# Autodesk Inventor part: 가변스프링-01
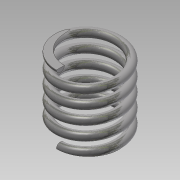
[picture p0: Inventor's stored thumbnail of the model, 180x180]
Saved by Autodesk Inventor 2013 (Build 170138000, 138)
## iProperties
Created: 2014-12
Part Number: 가변스프링-01
Material: 강철, 탄소
Document SubType Name: Modeling
Designer: hanacad19
Density: 7.87 g/cm^3
Mass: 18.7418 g
Surface Area: 32.4001 cm^2
Volume: 2.38143 cm^3
Author: hanacad19
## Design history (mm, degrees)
sketch "스케치1"
  geometry: L1 (0, 0)-(-11, 0); L2 (-11, 0)-(-11, 25.358); L3 (-11, 25.358)-(0, 25.358); L4 (0, 25.358)-(0, 0); C1 r 1.5 at (-11, 0)
  constraints: 8 end point, 2 parallel, 1 centre point, 1 horizontal, 1 perpendicular
  dimensions: "d0" = 3 diameter of C1; "d2" = 22 diameter of L2 L4; "d3" = 25.35829 distance between parallel lines of L1 L3 (derived)
feature "코일1" sketch "스케치1" pitch "d4" = 10; turns "d6" = 5; dims "d5" = 25.35829 (= d3), "d7" = 0, angle "d8" = 90 deg, angle "d9" = 90 deg, "d10" = 0, "d11" = 0
sketch "스케치2"
  geometry: L1 (0, -12.5)-(0, -9.5) reference; 1 further point
  constraints: 1 vertical alignment
extrude "돌출1" cut sketch "스케치2" distance "d12" = 10; taper "d13" = 0 deg
node "작업 평면1"
sketch "스케치3"
  geometry: L1 (0, -9.5)-(0, -12.5) reference; 1 further point
  constraints: 1 vertical alignment
extrude "돌출2" cut sketch "스케치3" distance "d14" = 10; taper "d15" = 0 deg
node "솔리드1"
node "절단 모서리 투영1"
node "절단 모서리 투영2"
